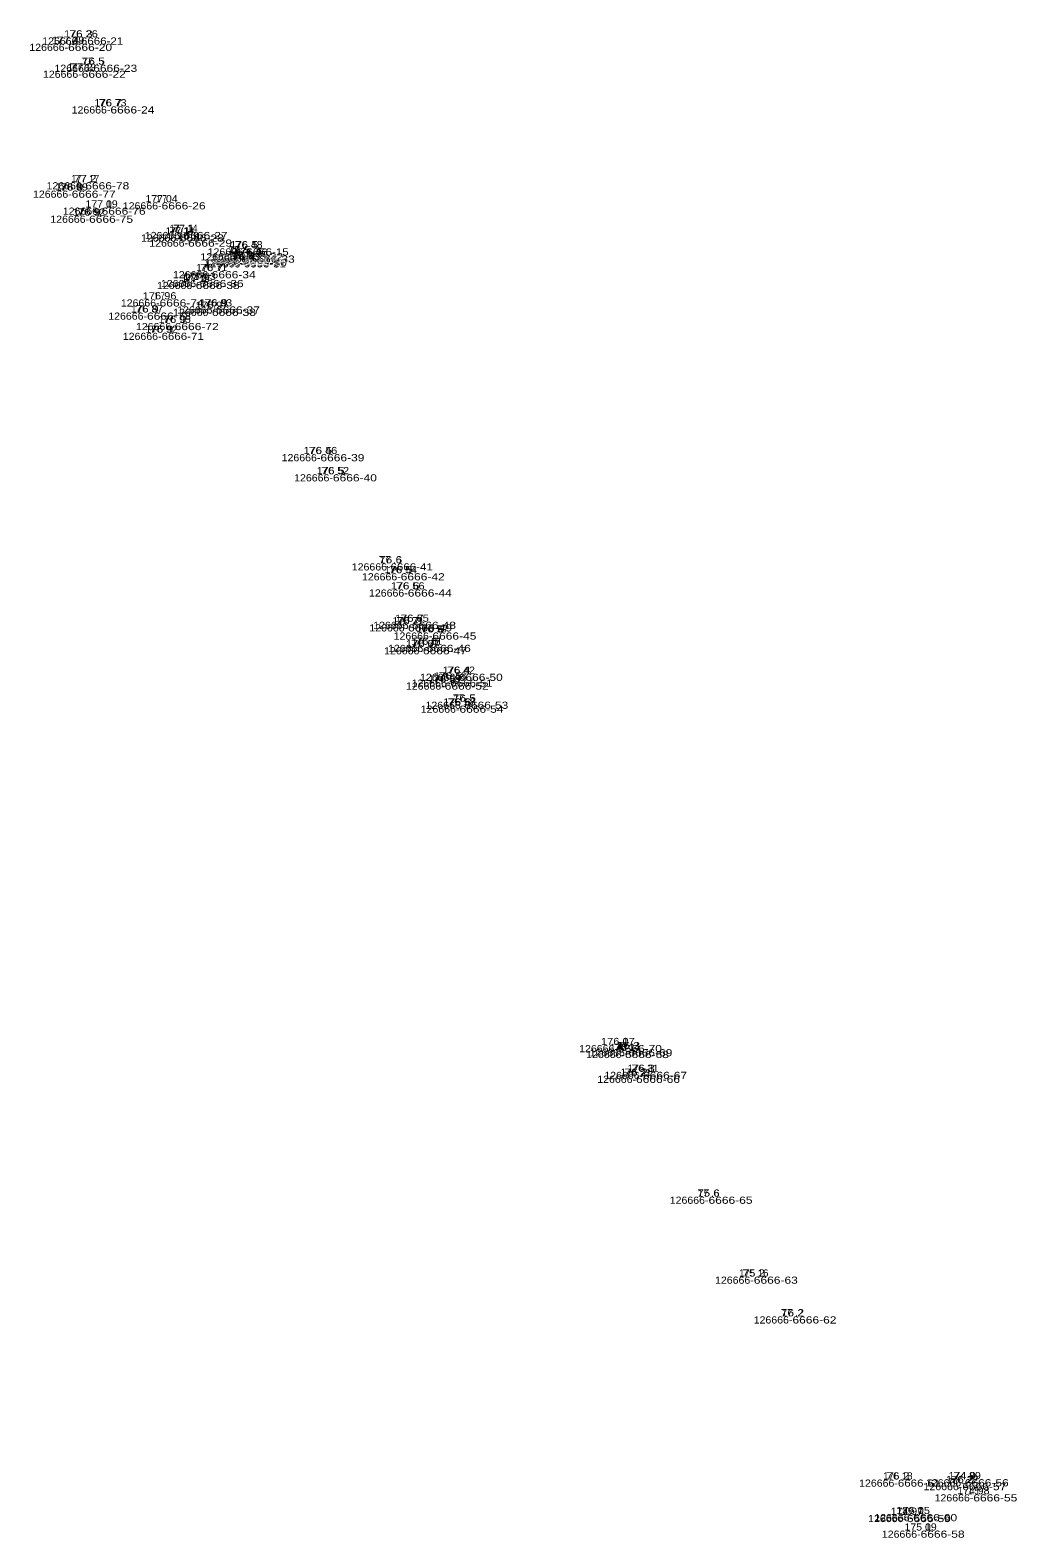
# Model space of a CAD drawing. Extents: x -598473 to -594209, y -1163589 to -1162143.
# Drawn here: x -594415.1 to -594208.9, y -1163589.2 to -1163274 of the extents above; entities that cross this region are included whole.
import ezdxf
from ezdxf.enums import TextEntityAlignment as Align

# ---------------------------------------------------------------- set-up
doc = ezdxf.new("R2010")
doc.units = 0
doc.header["$LTSCALE"] = 0.6
for name, color, linetype in [('57', 7, 'Continuous'), ('58', 7, 'Continuous'), ('61', 7, 'Continuous'), ('62', 7, 'Continuous')]:
    doc.layers.add(name, color=color, linetype=linetype)

msp = doc.modelspace()

# ---------------------------------------------------------------- texts
at = {"layer": '57'}
for s, width, p in [('77 4', 1.2, (-594407.198, -1163276.877)), ('76 3', 1.25, (-594404.508, -1163275.557)), ('76 5', 1.25, (-594401.948, -1163281.257)), ('77 2', 1.2, (-594404.348, -1163282.497)), ('76 7', 1.25, (-594398.348, -1163289.957)), ('77 2', 1.2, (-594403.608, -1163305.817)), ('76 9', 1.25, (-594406.438, -1163307.567)), ('1 7', 0.65, (-594387.6575, -1163310.007)), ('76 9', 1.25, (-594402.808, -1163312.807)), ('77 1', 1.1, (-594400.1985, -1163311.117)), ('77 1', 1.1, (-594383.0585, -1163316.207)), ('77 1', 1.1, (-594383.8485, -1163316.737)), ('76 9', 1.25, (-594382.118, -1163317.787)), ('76 5', 1.25, (-594371.428, -1163320.657)), ('76 5', 1.25, (-594370.648, -1163321.887)), ('76 4', 1.25, (-594370.488, -1163322.137)), ('76 5', 1.25, (-594369.918, -1163319.637)), ('76 5', 1.25, (-594369.018, -1163321.137)), ('76 7', 1.25, (-594377.178, -1163324.397)), ('77 2', 1.2, (-594380.518, -1163326.647)), ('1 7', 0.65, (-594379.6975, -1163326.247)), ('1 7', 0.65, (-594388.0675, -1163330.307)), ('76 9', 1.25, (-594376.288, -1163331.777)), ('76 9', 1.25, (-594390.698, -1163333.057)), ('76 9', 1.25, (-594384.908, -1163335.237)), ('1 7', 0.65, (-594377.1375, -1163332.277)), ('76 9', 1.25, (-594387.658, -1163337.287)), ('76 5', 1.25, (-594354.448, -1163362.647)), ('76 5', 1.25, (-594351.838, -1163366.857)), ('76 6', 1.25, (-594339.7875, -1163385.477)), ('76 5', 1.25, (-594337.658, -1163387.547)), ('76 6', 1.25, (-594336.1875, -1163390.937)), ('76 7', 1.25, (-594336.128, -1163398.227)), ('76 7', 1.25, (-594335.308, -1163397.697)), ('76 6', 1.25, (-594331.0375, -1163399.927)), ('76 7', 1.25, (-594333.028, -1163403.007)), ('76 6', 1.25, (-594332.2075, -1163402.507)), ('76 6', 1.25, (-594328.4675, -1163410.387)), ('76 5', 1.25, (-594327.288, -1163409.767)), ('76 4', 1.25, (-594325.528, -1163408.557)), ('76 6', 1.25, (-594325.3775, -1163415.217)), ('76 5', 1.25, (-594324.378, -1163414.397)), ('76 1', 1.15, (-594292.258, -1163486.167)), ('76 1', 1.15, (-594290.798, -1163487.397)), ('76 3', 1.25, (-594290.068, -1163487.037)), ('76 2', 1.25, (-594288.468, -1163492.587)), ('76 3', 1.25, (-594286.998, -1163491.767)), ('75 6', 1.2, (-594273.318, -1163517.857)), ('75 2', 1.2, (-594263.848, -1163534.567)), ('76 2', 1.25, (-594255.768, -1163542.877)), ('76 2', 1.25, (-594233.728, -1163576.987)), ('76 2', 1.25, (-594220.258, -1163577.717)), ('74 9', 1.2, (-594219.7575, -1163576.917)), ('1 5', 0.65, (-594217.9475, -1163580.067)), ('76 1', 1.15, (-594230.538, -1163584.207)), ('1 5', 0.65, (-594231.8475, -1163584.387)), ('75 1', 1.1, (-594228.9785, -1163587.657))]:
    msp.add_text(s, height=1.5, dxfattribs=dict(at, width=width)).set_placement(p, align=Align.CENTER)
at = {"layer": '58'}
for s, width, p in [('177 39', 1.1, (-594407.198, -1163276.877)), ('176 26', 1.15, (-594404.508, -1163275.557)), ('177 19', 0.95, (-594404.3475, -1163282.497)), ('176 73', 1.1, (-594398.348, -1163289.957)), ('177 17', 0.95, (-594403.6075, -1163305.817)), ('176 89', 1.1, (-594406.4375, -1163307.567)), ('177 04', 1.1, (-594387.6575, -1163310.007)), ('176 92', 1.1, (-594402.808, -1163312.807)), ('177 09', 1.1, (-594400.1975, -1163311.117)), ('177 14', 0.95, (-594383.0575, -1163316.207)), ('177 14', 0.95, (-594383.8475, -1163316.737)), ('176 43', 1.1, (-594370.488, -1163322.137)), ('176 48', 1.1, (-594369.918, -1163319.637)), ('176 46', 1.15, (-594369.018, -1163321.137)), ('176 71', 1.05, (-594377.1785, -1163324.397)), ('177 18', 0.95, (-594380.5175, -1163326.647)), ('177 03', 1.1, (-594379.6975, -1163326.247)), ('176 96', 1.15, (-594388.0685, -1163330.307)), ('176 93', 1.1, (-594376.288, -1163331.777)), ('176 87', 1.1, (-594390.698, -1163333.057)), ('176 95', 1.1, (-594384.908, -1163335.237)), ('176 97', 1.1, (-594377.138, -1163332.277)), ('176 92', 1.1, (-594387.658, -1163337.287)), ('176 46', 1.15, (-594354.448, -1163362.647)), ('176 52', 1.1, (-594351.838, -1163366.857)), ('176 54', 1.1, (-594337.658, -1163387.547)), ('176 56', 1.15, (-594336.188, -1163390.937)), ('176 71', 1.05, (-594336.1285, -1163398.227)), ('176 65', 1.15, (-594335.3085, -1163397.697)), ('176 57', 1.1, (-594331.038, -1163399.927)), ('176 67', 1.15, (-594333.0285, -1163403.007)), ('176 61', 1.05, (-594332.2075, -1163402.507)), ('176 59', 1.1, (-594328.4675, -1163410.387)), ('176 48', 1.1, (-594327.288, -1163409.767)), ('176 42', 1.1, (-594325.528, -1163408.557)), ('176 58', 1.1, (-594325.378, -1163415.217)), ('176 07', 1.15, (-594292.258, -1163486.167)), ('176 21', 1.05, (-594288.4685, -1163492.587)), ('176 31', 1.05, (-594286.9985, -1163491.767)), ('176 22', 1.1, (-594220.258, -1163577.717)), ('174 89', 1.1, (-594219.758, -1163576.917)), ('174 98', 1.1, (-594217.9485, -1163580.067)), ('176 05', 1.15, (-594230.538, -1163584.207)), ('174 97', 1.1, (-594231.8485, -1163584.387)), ('175 09', 1.1, (-594228.9775, -1163587.657))]:
    msp.add_text(s, height=1.5, dxfattribs=dict(at, width=width)).set_placement(p, align=Align.CENTER)
for s, p in [('17 .5', (-594401.948, -1163281.257)), ('17 .9', (-594382.1185, -1163317.787)), ('17 .5', (-594371.428, -1163320.657)), ('17 .5', (-594370.648, -1163321.887)), ('17 .6', (-594339.788, -1163385.477)), ('17 .5', (-594324.378, -1163414.397)), ('176 14', (-594290.798, -1163487.397)), ('17 .3', (-594290.068, -1163487.037)), ('17 .6', (-594273.318, -1163517.857)), ('175 16', (-594263.848, -1163534.567)), ('17 .2', (-594255.768, -1163542.877)), ('176 18', (-594233.728, -1163576.987))]:
    msp.add_text(s, height=1.5, dxfattribs=at).set_placement(p, align=Align.CENTER)
at = {"layer": '61', "width": 1.1}
for p in [(-594407.198, -1163278.377), (-594404.508, -1163277.057), (-594404.348, -1163283.997), (-594401.948, -1163282.757), (-594398.348, -1163291.457), (-594406.438, -1163309.067), (-594403.608, -1163307.317), (-594400.198, -1163312.617), (-594387.658, -1163311.507), (-594402.808, -1163314.307), (-594383.848, -1163318.237), (-594383.058, -1163317.707), (-594382.118, -1163319.287), (-594371.428, -1163322.157), (-594369.918, -1163321.137), (-594369.018, -1163322.637), (-594377.178, -1163325.897), (-594370.648, -1163323.387), (-594370.488, -1163323.637), (-594380.518, -1163328.147), (-594379.698, -1163327.747), (-594388.068, -1163331.807), (-594390.698, -1163334.557), (-594377.138, -1163333.777), (-594376.288, -1163333.277), (-594384.908, -1163336.737), (-594387.658, -1163338.787), (-594354.448, -1163364.147), (-594351.838, -1163368.357), (-594339.788, -1163386.977), (-594337.658, -1163389.047), (-594336.188, -1163392.437), (-594336.128, -1163399.727), (-594335.308, -1163399.197), (-594331.038, -1163401.427), (-594333.028, -1163404.507), (-594332.208, -1163404.007), (-594325.528, -1163410.057), (-594328.468, -1163411.887), (-594327.288, -1163411.267), (-594325.378, -1163416.717), (-594324.378, -1163415.897), (-594292.258, -1163487.667), (-594290.798, -1163488.897), (-594290.068, -1163488.537), (-594288.468, -1163494.087), (-594286.998, -1163493.267), (-594273.318, -1163519.357), (-594263.848, -1163536.067), (-594255.768, -1163544.377), (-594233.728, -1163578.487), (-594220.258, -1163579.217), (-594219.758, -1163578.417), (-594217.948, -1163581.567), (-594231.848, -1163585.887), (-594230.538, -1163585.707), (-594228.978, -1163589.157)]:
    msp.add_text('126666-', height=1.5, dxfattribs=at).set_placement(p, align=Align.RIGHT)
at = {"layer": '62'}
for s, width, p in [('6666-20', 1.25, (-594407.198, -1163278.377)), ('6666-21', 1.2, (-594404.508, -1163277.057)), ('6666-22', 1.25, (-594404.348, -1163283.997)), ('6666-23', 1.25, (-594401.948, -1163282.757)), ('6666-24', 1.25, (-594398.348, -1163291.457)), ('6666-77', 1.25, (-594406.438, -1163309.067)), ('6666-78', 1.25, (-594403.608, -1163307.317)), ('6666-76', 1.25, (-594400.198, -1163312.617)), ('6666-26', 1.25, (-594387.658, -1163311.507)), ('6666-75', 1.25, (-594402.808, -1163314.307)), ('6666-28', 1.25, (-594383.848, -1163318.237)), ('6666-27', 1.25, (-594383.058, -1163317.707)), ('6666-29', 1.25, (-594382.118, -1163319.287)), ('6666-32', 1.25, (-594371.428, -1163322.157)), ('6666-15', 1.2, (-594369.918, -1163321.137)), ('6666-33', 1.25, (-594369.018, -1163322.637)), ('6666-34', 1.25, (-594377.178, -1163325.897)), ('6666-30', 1.25, (-594370.648, -1163323.387)), ('6666-31', 1.2, (-594370.488, -1163323.637)), ('6666-35', 1.25, (-594380.518, -1163328.147)), ('6666-36', 1.25, (-594379.698, -1163327.747)), ('6666-74', 1.25, (-594388.068, -1163331.807)), ('6666-73', 1.25, (-594390.698, -1163334.557)), ('6666-38', 1.25, (-594377.138, -1163333.777)), ('6666-37', 1.25, (-594376.288, -1163333.277)), ('6666-72', 1.25, (-594384.908, -1163336.737)), ('6666-71', 1.2, (-594387.658, -1163338.787)), ('6666-39', 1.25, (-594354.448, -1163364.147)), ('6666-40', 1.25, (-594351.838, -1163368.357)), ('6666-41', 1.2, (-594339.788, -1163386.977)), ('6666-42', 1.25, (-594337.658, -1163389.047)), ('6666-44', 1.25, (-594336.188, -1163392.437)), ('6666-49', 1.25, (-594336.128, -1163399.727)), ('6666-48', 1.25, (-594335.308, -1163399.197)), ('6666-45', 1.25, (-594331.038, -1163401.427)), ('6666-47', 1.25, (-594333.028, -1163404.507)), ('6666-46', 1.25, (-594332.208, -1163404.007)), ('6666-50', 1.25, (-594325.528, -1163410.057)), ('6666-52', 1.25, (-594328.468, -1163411.887)), ('6666-51', 1.2, (-594327.288, -1163411.267)), ('6666-54', 1.25, (-594325.378, -1163416.717)), ('6666-53', 1.25, (-594324.378, -1163415.897)), ('6666-70', 1.25, (-594292.258, -1163487.667)), ('6666-68', 1.25, (-594290.798, -1163488.897)), ('6666-69', 1.25, (-594290.068, -1163488.537)), ('6666-66', 1.25, (-594288.468, -1163494.087)), ('6666-67', 1.25, (-594286.998, -1163493.267)), ('6666-65', 1.25, (-594273.318, -1163519.357)), ('6666-63', 1.25, (-594263.848, -1163536.067)), ('6666-62', 1.25, (-594255.768, -1163544.377)), ('6666-61', 1.2, (-594233.728, -1163578.487)), ('6666-57', 1.25, (-594220.258, -1163579.217)), ('6666-56', 1.25, (-594219.758, -1163578.417)), ('6666-55', 1.25, (-594217.948, -1163581.567)), ('6666-59', 1.25, (-594231.848, -1163585.887)), ('6666-60', 1.25, (-594230.538, -1163585.707)), ('6666-58', 1.25, (-594228.978, -1163589.157))]:
    msp.add_text(s, height=1.5, dxfattribs=dict(at, width=width)).set_placement(p)

doc.saveas('drawing.dxf')
